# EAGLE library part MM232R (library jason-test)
FTDI MM232R module
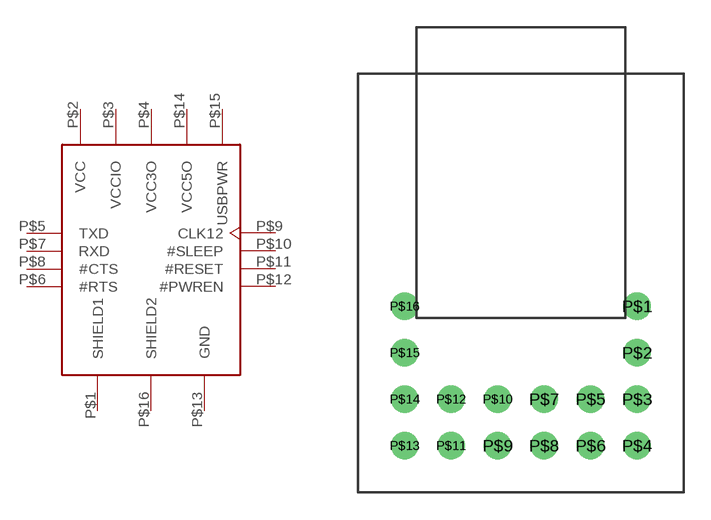
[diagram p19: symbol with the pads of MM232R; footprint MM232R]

Designator prefix -

## MM232R  [MM232R]
P$1  SHIELD1  pwr
P$2  VCC  pwr
P$3  VCCIO  pwr
P$4  VCC3O  pwr
P$5  TXD  out
P$6  #RTS  out
P$7  RXD  in
P$8  #CTS  in
P$9  CLK12  out
P$10  #SLEEP  out
P$11  #RESET  in
P$12  #PWREN  out
P$13  GND  pwr
P$14  VCC5O  pwr
P$15  USBPWR  pwr
P$16  SHIELD2  pwr

## Footprint MM232R (pad centres in mm)
drill 0.8 pad 1.5 round: P$1 6.35,0; P$2 6.35,-2.54; P$3 6.35,-5.08; P$4 6.35,-7.62; P$5 3.81,-5.08; P$6 3.81,-7.62; P$7 1.27,-5.08; P$8 1.27,-7.62; P$9 -1.27,-7.62; P$10 -1.27,-5.08; P$11 -3.81,-7.62; P$12 -3.81,-5.08; P$13 -6.35,-7.62; P$14 -6.35,-5.08; P$15 -6.35,-2.54; P$16 -6.35,0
